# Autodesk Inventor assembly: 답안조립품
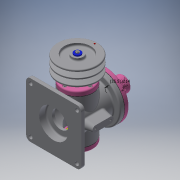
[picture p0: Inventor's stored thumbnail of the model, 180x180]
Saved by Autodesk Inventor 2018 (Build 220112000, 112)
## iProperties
Created: 2020-02
Part Number: 답안조립품
Document SubType Name: Assembly
Designer: Administrator
Mass: 1962.74 g
Surface Area: 2485.59 cm^2
Volume: 789.817 cm^3
Density: 2.48506 g/cm^3
Author: Administrator
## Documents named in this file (21)
- C:\Users\Administrator\Desktop\600206V1023\답안조립품.iam
- C:\Users\Administrator\Desktop\600206V1023\본체.ipt
- C:\Users\Administrator\Desktop\600206V1023\개스킷 B.ipt
- C:\Users\Administrator\Desktop\600206V1023\개스킷 A.ipt
- C:\Users\Administrator\Desktop\600206V1023\덮개.ipt
- C:\Users\Administrator\Desktop\600206V1023\앞커버.ipt
- C:\Users\Administrator\Desktop\600206V1023\뒤커버.ipt
- C:\Users\Administrator\Desktop\600206V1023\편심축.ipt
- C:\Users\Administrator\Desktop\600206V1023\베어링 17 x 40 x 12.ipt
- C:\Users\Administrator\Desktop\600206V1023\링크.ipt
- C:\Users\Administrator\Desktop\600206V1023\슬라이더.ipt
- C:\Users\Administrator\Desktop\600206V1023\클레비스 핀 6 x 22.ipt
- 클레비스 핀 6 x 22.ipt
- C:\Users\Administrator\Desktop\600206V1023\E-링.ipt
- C:\Users\Administrator\Desktop\600206V1023\오일 실 17 30 8.ipt
- C:\Users\Administrator\Desktop\600206V1023\키 4 x 4 x 25.ipt
- C:\Users\Administrator\Desktop\600206V1023\V-벨트풀리.ipt
- C:\Users\Administrator\Desktop\600206V1023\와셔 4x16.ipt
- C:\Users\Administrator\Desktop\600206V1023\볼트 M4 x 10.ipt
- C:\Users\Administrator\Desktop\600206V1023\육각 소켓 머리 볼트 M4 x 10.ipt
- C:\Users\Administrator\Desktop\600206V1023\가변스프링.ipt
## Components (6 placed, 5 different names)
1. 개스킷 B:1
2. 개스킷 A:1
3. 개스킷 A:2
4. E-링:1
5. V-벨트풀리:1
6. 가변스프링:1
